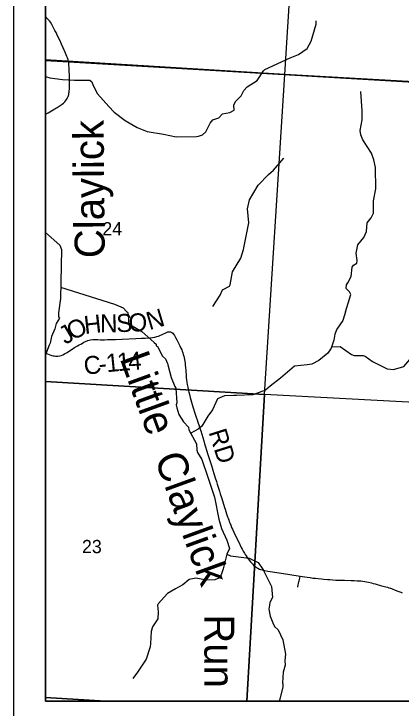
# Model space of a CAD drawing. Extents: x 0 to 34, y 0 to 22.
# Drawn here: x 23.417 to 24.638, y 14.078 to 16.271 of the extents above; entities that cross this region are included whole.
import ezdxf

# ---------------------------------------------------------------- set-up
doc = ezdxf.new("R2010")
doc.units = 0
for name, color, linetype in [('Default', 7, 'Continuous'), ('GM_X_County_Road', 7, 'Continuous'), ('GM_X_County_Road_Text', 7, 'Continuous'), ('GM_X_Minor_River', 7, 'Continuous'), ('GM_X_Minor_River_Text', 7, 'Continuous'), ('GM_X_Section', 7, 'Continuous'), ('GM_X_Section_Text', 7, 'Continuous'), ('GM_X_Township_Road', 7, 'Continuous'), ('SH_Data', 7, 'Continuous'), ('SH_Text', 7, 'Continuous')]:
    doc.layers.add(name, color=color, linetype=linetype)

msp = doc.modelspace()

# ---------------------------------------------------------------- linework, layer by layer
at = {"layer": 'Default'}
msp.add_lwpolyline([(27.7198, 20.9), (23.5167, 20.9), (23.5167, 16.1239), (23.5888, 16.1195), (25.0535, 16.0331), (25.3458, 16.0191), (26.0811, 15.9921), (26.3691, 15.9829), (26.8773, 15.953), (26.8866, 15.9536), (26.8953, 15.9537)], dxfattribs=at)
for points in [[(23.5167, 17.1515), (23.5167, 16.1254), (24.2716, 16.0795), (24.3357, 17.1007)], [(23.5167, 16.1254), (23.5167, 15.1095), (24.2076, 15.0689), (24.2716, 16.0795)], [(23.5167, 16.1239), (23.5167, 14.1), (26.2331, 14.1), (26.29, 15.0246), (26.3153, 15.3279), (26.3625, 15.9099), (26.3691, 15.9829), (26.0811, 15.9921), (25.3458, 16.0191), (25.0535, 16.0331), (23.5888, 16.1195)], [(23.5167, 15.1095), (23.5167, 14.1111), (23.7053, 14.1), (24.1517, 14.1), (24.2076, 15.0689)], [(24.1517, 14.1), (25.1974, 14.1), (25.2534, 15.0128), (24.2076, 15.0689)], [(23.5167, 14.1111), (23.5167, 14.1), (23.7053, 14.1)]]:
    msp.add_lwpolyline(points, close=True, dxfattribs=at)
at = {"layer": 'GM_X_County_Road'}
for points in [[(23.589, 16.1189), (23.5886, 16.1211), (23.5878, 16.125), (23.5859, 16.1314), (23.5841, 16.1364), (23.5798, 16.147), (23.5721, 16.1636), (23.5666, 16.1754), (23.5611, 16.1872), (23.5543, 16.2017), (23.5497, 16.2114), (23.5463, 16.2182), (23.541, 16.2289), (23.5367, 16.2369), (23.5317, 16.2442), (23.5285, 16.2484), (23.525, 16.2525), (23.521, 16.2575), (23.5179, 16.261), (23.5167, 16.2623)], [(23.5167, 15.9538), (23.5252, 15.9586), (23.546, 15.9711), (23.5492, 15.9729), (23.5535, 15.9753), (23.5623, 15.9809), (23.569, 15.9853), (23.5736, 15.9888), (23.5772, 15.9923), (23.581, 15.9974), (23.583, 16.0006), (23.5846, 16.0033), (23.5875, 16.0096), (23.5895, 16.0156), (23.5905, 16.0206), (23.591, 16.0238), (23.5913, 16.0268), (23.5914, 16.028), (23.5916, 16.0327), (23.5918, 16.0368), (23.5919, 16.0424), (23.5918, 16.0512), (23.5917, 16.0585), (23.5917, 16.0635), (23.5917, 16.0685), (23.5916, 16.0728), (23.5916, 16.0804), (23.5915, 16.0871), (23.5914, 16.0919), (23.5912, 16.0965), (23.5909, 16.1014), (23.5905, 16.1077), (23.5898, 16.1147), (23.589, 16.1189)], [(23.5167, 15.1984), (23.5223, 15.1964), (23.528, 15.1945), (23.5329, 15.1929), (23.5364, 15.192), (23.5403, 15.191), (23.5437, 15.1905), (23.5484, 15.1899), (23.5553, 15.1897), (23.5616, 15.1905), (23.5659, 15.1918), (23.5706, 15.1936), (23.5767, 15.1968), (23.5843, 15.2016), (23.5923, 15.2065), (23.6002, 15.2114), (23.6082, 15.2164), (23.6168, 15.2217), (23.6225, 15.225), (23.6276, 15.2279), (23.633, 15.2309), (23.6377, 15.2333), (23.6423, 15.2357), (23.6503, 15.2389), (23.6579, 15.241), (23.6652, 15.2419), (23.6713, 15.2421), (23.6812, 15.2418), (23.6899, 15.2416), (23.6967, 15.2416), (23.7029, 15.2416), (23.7116, 15.2417), (23.7377, 15.2424), (23.7582, 15.2432), (23.8017, 15.2453), (23.819, 15.2461), (23.8307, 15.2467), (23.8388, 15.2472), (23.8451, 15.2477), (23.8539, 15.2485), (23.8613, 15.2495), (23.8673, 15.2511), (23.8733, 15.2531), (23.8773, 15.2548), (23.8825, 15.2569), (23.8883, 15.2598), (23.8939, 15.2625), (23.8976, 15.2643), (23.9027, 15.2661), (23.9073, 15.2666), (23.9112, 15.266), (23.9149, 15.2642), (23.9178, 15.2621), (23.9206, 15.2589), (23.9236, 15.2543), (23.9265, 15.2488), (23.9308, 15.2407), (23.9338, 15.2345), (23.9369, 15.2282), (23.94, 15.2217), (23.9432, 15.2152), (23.946, 15.2094), (23.9477, 15.2049), (23.9498, 15.1997), (23.9511, 15.1951), (23.9529, 15.189), (23.9539, 15.1842), (23.9551, 15.1787), (23.9558, 15.1734), (23.9568, 15.1665), (23.9572, 15.1611), (23.9579, 15.1533), (23.9587, 15.1449), (23.9591, 15.1395), (23.9598, 15.1306), (23.9605, 15.1225), (23.9614, 15.1146), (23.9624, 15.1058), (23.9633, 15.1003), (23.965, 15.0911), (23.9666, 15.0844), (23.9686, 15.076), (23.9706, 15.0688), (23.9732, 15.0591), (23.9754, 15.0514), (23.9817, 15.0292), (23.9888, 15.0067), (23.9922, 14.9967), (23.995, 14.9884), (23.9974, 14.9808), (24.0011, 14.9693), (24.0028, 14.9642), (24.0045, 14.9589), (24.0062, 14.9533), (24.0094, 14.9427), (24.0127, 14.9322), (24.0157, 14.9221), (24.0185, 14.9125), (24.0215, 14.903), (24.0248, 14.8925), (24.029, 14.8792), (24.032, 14.8698), (24.036, 14.8571), (24.0401, 14.8438), (24.0446, 14.8295), (24.0478, 14.8193), (24.052, 14.8055), (24.0556, 14.7939), (24.0583, 14.785), (24.0604, 14.7784), (24.0632, 14.7696), (24.0652, 14.7632), (24.0678, 14.7547), (24.069, 14.751), (24.0706, 14.7458), (24.0724, 14.7401), (24.0814, 14.7114), (24.0831, 14.706), (24.0855, 14.6988), (24.0879, 14.6914), (24.0898, 14.6855), (24.0918, 14.6795), (24.0929, 14.6762), (24.0943, 14.6722), (24.0962, 14.6673), (24.0977, 14.6631), (24.1006, 14.6562), (24.1037, 14.6487), (24.1064, 14.6428), (24.1105, 14.6341), (24.1162, 14.6224), (24.126, 14.6022), (24.1342, 14.5855), (24.137, 14.58), (24.1405, 14.5736), (24.1437, 14.5675), (24.1465, 14.5627), (24.149, 14.5584), (24.1525, 14.5532), (24.1544, 14.5507)], [(24.1544, 14.5507), (24.1557, 14.549), (24.1586, 14.5453), (24.1631, 14.5401), (24.1663, 14.5365), (24.1702, 14.5322), (24.1729, 14.5296), (24.1776, 14.5254), (24.1822, 14.5222), (24.1864, 14.5194), (24.1916, 14.5169), (24.1952, 14.5156), (24.1999, 14.5141), (24.2085, 14.5123), (24.2175, 14.5108), (24.2257, 14.5094), (24.2668, 14.5029), (24.2871, 14.4997), (24.3199, 14.4946), (24.3417, 14.4914), (24.3512, 14.4899), (24.3599, 14.4888), (24.3679, 14.4878), (24.3767, 14.487), (24.3871, 14.486), (24.3941, 14.4855), (24.4059, 14.4845), (24.413, 14.4839), (24.4234, 14.4832), (24.4322, 14.4825), (24.4389, 14.4822), (24.4459, 14.4818), (24.4512, 14.4817), (24.4599, 14.4815), (24.4807, 14.481), (24.4906, 14.4808), (24.4992, 14.4803), (24.5039, 14.48), (24.5109, 14.4795), (24.5178, 14.4785), (24.5243, 14.4775), (24.5295, 14.4765), (24.5353, 14.4754), (24.5444, 14.4732), (24.5497, 14.4719), (24.5565, 14.4701), (24.5623, 14.4686), (24.5696, 14.4665), (24.5766, 14.4646), (24.5822, 14.4631), (24.5896, 14.461), (24.5955, 14.4594), (24.5998, 14.4582), (24.6044, 14.4566), (24.6084, 14.4552), (24.6119, 14.4538), (24.6171, 14.4517), (24.6245, 14.4485), (24.6314, 14.4457), (24.6371, 14.4437), (24.6419, 14.442)]]:
    msp.add_lwpolyline(points, dxfattribs=at)
at = {"layer": 'GM_X_Minor_River'}
for points in [[(23.5167, 16.0733), (23.5298, 16.0691), (23.57, 16.0631), (23.6075, 16.0616), (23.656, 16.0616), (23.6625, 16.0556), (23.6663, 16.0442), (23.6799, 16.0176), (23.7163, 15.9777), (23.7333, 15.9602), (23.7682, 15.9336), (23.8057, 15.9113), (23.8368, 15.8995), (23.8887, 15.8904), (23.9289, 15.8825), (23.9926, 15.8833), (23.999, 15.8849), (24.0115, 15.8891), (24.0222, 15.8982), (24.0358, 15.9252), (24.0445, 15.9355), (24.0627, 15.9427), (24.0752, 15.9549), (24.098, 15.9595), (24.1113, 15.9663), (24.1109, 15.9819), (24.1154, 15.9941), (24.1336, 16.012), (24.1424, 16.0287), (24.153, 16.0398), (24.1837, 16.0607), (24.2042, 16.0912), (24.208, 16.0946), (24.2883, 16.1323), (24.3145, 16.1422), (24.3418, 16.1609), (24.3543, 16.1841), (24.3699, 16.2381), (24.3703, 16.2489)], [(24.4629, 15.3291), (24.4795, 15.3843), (24.4753, 15.393), (24.4647, 15.4036), (24.4659, 15.4143), (24.47, 15.4215), (24.481, 15.4413), (24.4841, 15.4702), (24.4879, 15.477), (24.4981, 15.4831), (24.4993, 15.4915), (24.4966, 15.5151), (24.5015, 15.5413), (24.5209, 15.5645), (24.5292, 15.5832), (24.5315, 15.6102), (24.544, 15.6265), (24.5509, 15.6414), (24.5516, 15.6452), (24.5516, 15.6798), (24.5581, 15.7178), (24.5577, 15.7858), (24.5521, 15.8094), (24.5452, 15.8311), (24.5176, 15.8733), (24.5115, 15.8888), (24.5093, 15.9025), (24.515, 15.9364), (24.5153, 15.9641), (24.5108, 16.0253)], [(24.0444, 15.3468), (24.0671, 15.3819), (24.0743, 15.3994), (24.0966, 15.4105), (24.0989, 15.4143), (24.1065, 15.4557), (24.1323, 15.4991), (24.1414, 15.5261), (24.1578, 15.6109), (24.1536, 15.655), (24.1601, 15.6831), (24.187, 15.7299), (24.2196, 15.7638), (24.2355, 15.7768), (24.2678, 15.8152)], [(23.5167, 15.5801), (23.5617, 15.5405), (23.5664, 15.5265), (23.5634, 15.3721)], [(23.5641, 15.4078), (23.7345, 15.3542), (23.7614, 15.3418)], [(23.5634, 15.3721), (23.5571, 15.3265), (23.5571, 15.314), (23.5601, 15.309), (23.5496, 15.2923), (23.5454, 15.2759), (23.5348, 15.2519), (23.5315, 15.2307), (23.5277, 15.2238), (23.5167, 15.1941)], [(23.7614, 15.3418), (23.7714, 15.3301), (23.7748, 15.3282), (23.7778, 15.3183), (23.7782, 15.2944), (23.7843, 15.2883), (23.8199, 15.2675), (23.8592, 15.2322), (23.866, 15.2269), (23.866, 15.222), (23.8694, 15.2201), (23.8857, 15.1893), (23.8948, 15.1806), (23.9008, 15.1662), (23.9027, 15.1616), (23.913, 15.1217), (23.9243, 15.0936), (23.9278, 15.0883), (23.9312, 15.042), (23.9286, 15.0363), (23.9312, 15.026), (23.9369, 15.0051), (23.9513, 14.9823), (23.9672, 14.9657), (23.9687, 14.9573), (23.9926, 14.9121), (23.9933, 14.8931), (23.996, 14.8851), (24.0096, 14.8631), (24.0278, 14.8107), (24.0498, 14.7446), (24.0635, 14.6751), (24.0718, 14.6447), (24.0885, 14.6083), (24.0968, 14.5817), (24.0882, 14.5642), (24.0999, 14.5585), (24.1589, 14.5514), (24.1872, 14.5378), (24.2031, 14.5143), (24.2285, 14.4645), (24.2293, 14.4615), (24.2323, 14.4273), (24.2244, 14.4113), (24.2233, 14.4026), (24.2214, 14.3908), (24.2248, 14.368), (24.2335, 14.3471), (24.2392, 14.3357), (24.2505, 14.3255), (24.2653, 14.294), (24.2737, 14.2484), (24.2711, 14.2286), (24.2726, 14.2138), (24.2666, 14.191), (24.2643, 14.1575), (24.2647, 14.1548), (24.2647, 14.1446), (24.2553, 14.1058), (24.2534, 14.1)], [(24.4629, 15.3291), (24.4549, 15.3024), (24.4352, 15.2753), (24.4287, 15.2588), (24.4258, 15.2399), (24.4175, 15.2144), (24.4068, 15.1995), (24.3789, 15.1753), (24.3562, 15.1639), (24.3422, 15.1621), (24.302, 15.1584), (24.2581, 15.1196), (24.2249, 15.0948), (24.2105, 15.0824), (24.1704, 15.0677), (24.1189, 15.0648), (24.111, 15.0654), (24.0807, 15.0645), (24.0592, 15.0545), (24.0431, 15.0205), (24.0288, 14.9997), (24.0094, 14.9684), (23.9977, 14.9585), (23.9744, 14.9464)], [(24.419, 15.219), (24.446, 15.2199), (24.4815, 15.1949), (24.4905, 15.1919), (24.5181, 15.1914), (24.5252, 15.1893), (24.5481, 15.1722), (24.5943, 15.1499), (24.6147, 15.1477), (24.6471, 15.1565), (24.6851, 15.2013), (24.7134, 15.2239), (24.7408, 15.2553), (24.784, 15.2725), (24.82, 15.301), (24.8246, 15.3031), (24.8453, 15.3249), (24.8495, 15.3368)], [(24.0882, 14.5642), (24.077, 14.5174), (24.0707, 14.499), (24.0632, 14.4882), (24.051, 14.4833), (24.0245, 14.4815), (23.9906, 14.4882), (23.9697, 14.4836), (23.9499, 14.4668), (23.9261, 14.455), (23.9015, 14.4402), (23.8718, 14.4073), (23.8697, 14.4025), (23.8718, 14.3819), (23.8711, 14.3595), (23.8537, 14.3346), (23.8495, 14.32), (23.8472, 14.2824), (23.8465, 14.2718), (23.8336, 14.232), (23.8066, 14.1911), (23.7924, 14.171)]]:
    msp.add_lwpolyline(points, dxfattribs=at)
at = {"layer": 'GM_X_Section'}
for points in [[(24.3357, 17.1007), (25.3722, 17.0086), (25.3091, 16.0203), (24.2716, 16.0795)], [(24.2716, 16.0795), (25.3091, 16.0203), (25.2534, 15.0128), (24.2076, 15.0689)]]:
    msp.add_lwpolyline(points, close=True, dxfattribs=at)
at = {"layer": 'GM_X_Township_Road'}
msp.add_lwpolyline([(24.312, 14.4597), (24.3139, 14.4676), (24.3148, 14.4715), (24.3158, 14.4764), (24.3166, 14.48), (24.3176, 14.4843), (24.3185, 14.4882), (24.3199, 14.4946)], dxfattribs=at)
at = {"layer": 'SH_Data'}
for points in [[(23.4167, 21), (30.4167, 21), (30.4167, 14), (23.4167, 14)], [(23.5167, 20.9), (30.3167, 20.9), (30.3167, 14.1), (23.5167, 14.1)]]:
    msp.add_lwpolyline(points, close=True, dxfattribs=at)
at = {"layer": 'SH_Text'}
msp.add_lwpolyline([(30.3167, 20.9), (23.5167, 20.9), (23.5167, 14.1), (29.5051, 14.1)], dxfattribs=at)

# ---------------------------------------------------------------- texts
at = {"layer": 'GM_X_County_Road_Text'}
for s, height, rotation, p in [('N', 0.0568, 16.5268, (23.8443, 15.2714)), ('O', 0.0568, 27.4823, (23.6015, 15.2378)), ('H', 0.0568, 6.267, (23.6406, 15.2592)), ('N', 0.0568, 0.3752, (23.6888, 15.2646)), ('S', 0.0568, 2.2013, (23.7407, 15.265)), ('O', 0.0568, 2.752, (23.7796, 15.2665)), ('J', 0.0568, 30.3125, (23.5792, 15.2247)), ('1', 0.0568, 5.7209, (23.7098, 15.1386)), ('1', 0.0568, 4.7515, (23.7443, 15.1421)), ('4', 0.0568, 3.3897, (23.7788, 15.1449)), ('C', 0.0568, 7.1216, (23.6406, 15.1301)), ('-', 0.0568, 6.6893, (23.6868, 15.1359)), ('RD', 0.05682, 287.5008, (24.0305, 14.9498))]:
    msp.add_text(s, height=height, rotation=rotation, dxfattribs=at).set_placement(p)
at = {"layer": 'GM_X_Minor_River_Text'}
for s, rotation, p in [('Claylick', 90.5134, (23.7035, 15.4994)), ('Little', 289.9986, (23.7496, 15.1833)), ('Claylick', 289.9986, (23.8593, 14.8677)), ('Run', 269.9991, (24.0177, 14.3742))]:
    msp.add_text(s, height=0.0947, rotation=rotation, dxfattribs=at).set_placement(p)
at = {"layer": 'GM_X_Section_Text'}
for s, p in [('24', (23.6958, 15.5709)), ('23', (23.6316, 14.5673))]:
    msp.add_text(s, height=0.04186, rotation=0, dxfattribs=at).set_placement(p)

doc.saveas('drawing.dxf')
